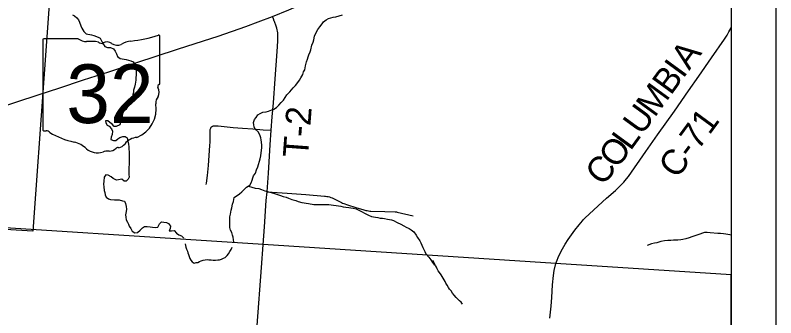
# Model space of a CAD drawing. Extents: x -8.2 to 34, y 0 to 22.
# Drawn here: x 7.291 to 9, y 15.27 to 15.949 of the extents above; entities that cross this region are included whole.
import ezdxf

# ---------------------------------------------------------------- set-up
doc = ezdxf.new("R2010")
doc.units = 0
for name, color, linetype in [('GM_X_Corporation', 7, 'Continuous'), ('GM_X_County_Road', 7, 'Continuous'), ('GM_X_County_Road_Text', 7, 'Continuous'), ('GM_X_Minor_River', 7, 'Continuous'), ('GM_X_State_Location', 7, 'Continuous'), ('GM_X_State_Route', 7, 'Continuous'), ('GM_X_State_Shield', 7, 'Continuous'), ('GM_X_Township_Road', 7, 'Continuous'), ('GM_X_Township_Road_Text', 7, 'Continuous'), ('GM_X_Township_Text', 7, 'Continuous'), ('SH_Data', 7, 'Continuous')]:
    doc.layers.add(name, color=color, linetype=linetype)

msp = doc.modelspace()

# ---------------------------------------------------------------- linework, layer by layer
at = {"layer": 'GM_X_Corporation'}
for points in [[(6.3752, 16.558), (7.4018, 16.494), (7.4044, 16.4939), (7.3299, 15.4643), (6.2993, 15.5265)], [(4.1481, 14.1), (8.9, 14.1), (8.9, 15.3663), (8.5054, 15.392), (7.8479, 15.4343), (7.082, 15.4841), (6.7558, 15.5053), (6.7389, 15.5064), (6.2987, 15.5287), (5.4088, 15.5882), (4.4836, 15.6492), (4.4152, 15.6505), (4.2922, 15.6569), (4.2674, 15.658), (4.2558, 15.6585), (4.2352, 15.4906), (4.2113, 15.0848), (4.1846, 14.6878), (4.1741, 14.5315), (4.1604, 14.3288)]]:
    msp.add_lwpolyline(points, close=True, dxfattribs=at)
at = {"layer": 'GM_X_County_Road'}
for points in [[(8.5057, 15.3914), (8.5086, 15.3992), (8.5112, 15.4049), (8.5165, 15.4161), (8.5207, 15.4244), (8.5269, 15.4351), (8.5334, 15.4456), (8.5408, 15.4564), (8.5482, 15.4663), (8.5579, 15.4784), (8.5655, 15.4874), (8.5681, 15.4903), (8.571, 15.4932), (8.5812, 15.5032), (8.6195, 15.5385), (8.6396, 15.556), (8.6487, 15.5645), (8.6531, 15.5689), (8.6582, 15.5744), (8.6642, 15.5815), (8.6687, 15.5874), (8.7079, 15.6433), (8.7339, 15.6804), (8.7721, 15.7341), (8.8039, 15.7793), (8.8268, 15.8125), (8.8553, 15.8539), (8.8847, 15.8956), (8.8904, 15.9044), (8.8948, 15.912), (8.8986, 15.9192), (8.9, 15.9225)], [(8.4924, 15.2686), (8.4953, 15.2956), (8.4969, 15.3155), (8.4978, 15.3438), (8.5001, 15.3647), (8.5018, 15.3762), (8.5057, 15.3914)]]:
    msp.add_lwpolyline(points, dxfattribs=at)
at = {"layer": 'GM_X_Minor_River'}
for points in [[(7.4191, 15.9504), (7.424, 15.9481), (7.4289, 15.9435), (7.4327, 15.9386), (7.4349, 15.9336), (7.4383, 15.9252), (7.4406, 15.9199), (7.4451, 15.913), (7.4504, 15.9077), (7.4618, 15.9053), (7.4671, 15.9041), (7.477, 15.9003), (7.4819, 15.8976), (7.4856, 15.8904), (7.4883, 15.8854), (7.4924, 15.8793), (7.4977, 15.8766), (7.505, 15.8766), (7.5118, 15.8735), (7.5152, 15.8689), (7.5186, 15.8624), (7.5208, 15.8563), (7.5265, 15.8521), (7.5402, 15.8497), (7.5504, 15.8466), (7.5554, 15.8447), (7.5595, 15.8394), (7.5606, 15.8337), (7.5617, 15.8283), (7.5625, 15.8219), (7.5624, 15.8146), (7.5616, 15.8093), (7.5616, 15.8036), (7.56, 15.7945), (7.5588, 15.788), (7.5565, 15.7808), (7.5561, 15.7758), (7.5553, 15.7713), (7.5542, 15.7667), (7.553, 15.7618), (7.5507, 15.7561), (7.548, 15.7496), (7.543, 15.7432), (7.5392, 15.7375), (7.5346, 15.7337), (7.5315, 15.7288), (7.5307, 15.7231), (7.5303, 15.7155), (7.5276, 15.7086), (7.5257, 15.7033), (7.5173, 15.6992), (7.5127, 15.6992), (7.5082, 15.7045), (7.5036, 15.708), (7.4987, 15.7118), (7.4934, 15.7119), (7.4941, 15.7073), (7.4971, 15.7027), (7.5021, 15.7), (7.5073, 15.6943), (7.5096, 15.6886), (7.5088, 15.6813), (7.5061, 15.6753), (7.5053, 15.6699), (7.5114, 15.6676), (7.5167, 15.668), (7.5213, 15.6714), (7.5259, 15.6748), (7.5323, 15.677), (7.5377, 15.6766), (7.5422, 15.6736), (7.5441, 15.6667), (7.5456, 15.6595), (7.5459, 15.6538), (7.5463, 15.6484), (7.547, 15.6427), (7.5469, 15.634), (7.5465, 15.6264)], [(7.7815, 15.4394), (7.7816, 15.4402), (7.7812, 15.4448), (7.7805, 15.4505), (7.779, 15.4555), (7.7772, 15.4612), (7.7745, 15.4665), (7.773, 15.4722), (7.7727, 15.4806), (7.7727, 15.4852), (7.7731, 15.4909), (7.7732, 15.4962), (7.7743, 15.5023), (7.7751, 15.5069), (7.7763, 15.5114), (7.7775, 15.5164), (7.779, 15.5247), (7.7814, 15.5308), (7.7829, 15.5403), (7.7944, 15.5478), (7.7997, 15.5528), (7.8051, 15.5581), (7.8108, 15.563), (7.8177, 15.5675), (7.8208, 15.5728), (7.8235, 15.5785), (7.8243, 15.5838), (7.8262, 15.5884), (7.8308, 15.5948), (7.8331, 15.6021), (7.8362, 15.6085), (7.8377, 15.6138), (7.8393, 15.6218), (7.8412, 15.6268), (7.8428, 15.6336), (7.8436, 15.6401), (7.8452, 15.6515), (7.8448, 15.6579), (7.8434, 15.6694), (7.8426, 15.6743), (7.8404, 15.6808), (7.8363, 15.6873), (7.8302, 15.6934), (7.828, 15.6987), (7.8268, 15.7033), (7.8261, 15.7086), (7.8284, 15.7151), (7.8323, 15.7196), (7.8361, 15.7257), (7.8411, 15.7287), (7.8475, 15.7314), (7.8544, 15.7325), (7.8597, 15.734), (7.8673, 15.737), (7.8719, 15.7381), (7.8776, 15.7419), (7.8834, 15.7475), (7.8883, 15.7532), (7.8933, 15.7589), (7.8972, 15.7642), (7.9014, 15.7703), (7.9079, 15.7771), (7.9117, 15.782), (7.9152, 15.7866), (7.9205, 15.7915), (7.9255, 15.7983), (7.9293, 15.8036), (7.9328, 15.8085), (7.937, 15.8165), (7.9389, 15.8218), (7.9412, 15.8268), (7.942, 15.8313), (7.9428, 15.8359), (7.9451, 15.8446), (7.9475, 15.8503), (7.949, 15.8557), (7.9506, 15.8606), (7.9533, 15.867), (7.9548, 15.8716), (7.9575, 15.8819), (7.9599, 15.8891), (7.9618, 15.8944), (7.9634, 15.902), (7.9672, 15.9107), (7.9707, 15.9176), (7.9749, 15.9229), (7.9802, 15.9297), (7.9833, 15.9346), (7.9894, 15.9392), (7.9951, 15.9422), (8.0001, 15.9437), (8.0054, 15.9448), (8.0111, 15.9459), (8.0188, 15.9481), (8.026, 15.95)], [(7.5465, 15.6264), (7.5464, 15.6134), (7.546, 15.6089), (7.546, 15.602), (7.5463, 15.5917), (7.5467, 15.5856), (7.5447, 15.5811), (7.5398, 15.5765), (7.5352, 15.5769), (7.5299, 15.5808), (7.5227, 15.5797), (7.5181, 15.5789), (7.5109, 15.5828), (7.506, 15.5866), (7.4999, 15.5901), (7.4942, 15.5905), (7.4908, 15.5855), (7.4896, 15.5764), (7.4891, 15.5699), (7.4895, 15.5639), (7.4906, 15.5559), (7.4917, 15.5513), (7.4928, 15.546), (7.4947, 15.5406), (7.5004, 15.5372), (7.5049, 15.5352), (7.5137, 15.5348), (7.5239, 15.5348), (7.5315, 15.5328), (7.5365, 15.5317), (7.5383, 15.5263), (7.5402, 15.5195), (7.5405, 15.5141), (7.5397, 15.5084), (7.5386, 15.5008), (7.5393, 15.4955), (7.54, 15.4898), (7.543, 15.4848), (7.5449, 15.4799), (7.5468, 15.4753), (7.5502, 15.4703), (7.5536, 15.4642), (7.5592, 15.4604), (7.5657, 15.4611), (7.5715, 15.4664), (7.5764, 15.4717), (7.5814, 15.4751), (7.5871, 15.4747), (7.5939, 15.4743), (7.5993, 15.4735), (7.6065, 15.4723), (7.611, 15.4731), (7.6149, 15.4807), (7.6191, 15.4852), (7.6248, 15.4848), (7.6305, 15.4836), (7.6354, 15.4817), (7.64, 15.4756), (7.6388, 15.4706), (7.6369, 15.4653), (7.6418, 15.4653), (7.6475, 15.466), (7.6528, 15.4599), (7.6585, 15.4561), (7.6642, 15.4541), (7.6691, 15.4492), (7.6692, 15.4489)], [(7.8148, 15.5656), (7.8302, 15.5606), (7.8382, 15.5598), (7.8443, 15.5579), (7.8518, 15.5552), (7.8579, 15.5536), (7.8629, 15.5521), (7.8682, 15.5501), (7.8731, 15.549), (7.8822, 15.5459), (7.8872, 15.5443), (7.8925, 15.5424), (7.8993, 15.5405), (7.9046, 15.5385), (7.9126, 15.5358), (7.9213, 15.5331), (7.9266, 15.5312), (7.935, 15.5289), (7.9399, 15.5281), (7.9445, 15.5269), (7.9498, 15.5261), (7.962, 15.5245), (7.9673, 15.5241), (7.9768, 15.5241), (7.9829, 15.5244), (7.9909, 15.5244), (7.9954, 15.524), (8.0004, 15.5236), (8.0061, 15.5228), (8.0121, 15.522), (8.0171, 15.5212), (8.0224, 15.5204), (8.0277, 15.5193), (8.0338, 15.5185), (8.0403, 15.5177), (8.0452, 15.5169), (8.0498, 15.5161), (8.057, 15.5142), (8.0646, 15.5107), (8.0691, 15.5088), (8.0774, 15.5042), (8.0846, 15.5003), (8.0911, 15.4976), (8.1002, 15.4957), (8.1055, 15.4949), (8.1112, 15.4937), (8.1162, 15.4933), (8.1207, 15.4925), (8.1272, 15.4914), (8.1363, 15.4894), (8.1409, 15.4879), (8.1492, 15.484), (8.1572, 15.4802), (8.1644, 15.4763), (8.1693, 15.4733), (8.1757, 15.4702), (8.1807, 15.4671), (8.1867, 15.4625), (8.192, 15.4557), (8.1946, 15.4503), (8.2003, 15.4427), (8.2026, 15.4381), (8.2044, 15.4331), (8.2071, 15.4278), (8.2093, 15.4228), (8.2112, 15.4183), (8.2138, 15.4137), (8.2199, 15.4057), (8.2244, 15.3996), (8.2282, 15.3942), (8.2331, 15.3877)], [(8.9, 15.4556), (8.8967, 15.4559), (8.8879, 15.4575), (8.8822, 15.4582), (8.8754, 15.459), (8.8697, 15.4594), (8.8522, 15.4603), (8.8461, 15.4611), (8.84, 15.4611), (8.8351, 15.46), (8.8294, 15.4577), (8.8202, 15.4547), (8.8111, 15.4514), (8.8054, 15.4495), (8.7981, 15.4473), (8.7913, 15.4454), (8.7867, 15.4446), (8.7799, 15.4443), (8.7753, 15.4443), (8.77, 15.444), (8.7639, 15.4436), (8.757, 15.4437), (8.7498, 15.4429), (8.7418, 15.4411), (8.733, 15.4384), (8.7273, 15.4373), (8.7209, 15.4358), (8.7106, 15.4325)], [(7.6725, 15.4359), (7.674, 15.4284), (7.6756, 15.4239), (7.6775, 15.4197), (7.6783, 15.4155), (7.6798, 15.4117), (7.6813, 15.4072), (7.6832, 15.403), (7.6855, 15.3992), (7.6882, 15.3954), (7.6928, 15.3928), (7.6973, 15.3936), (7.7011, 15.3943), (7.7049, 15.3962), (7.7087, 15.3974), (7.7129, 15.3993), (7.7174, 15.3997), (7.7224, 15.4008), (7.7261, 15.4001), (7.7311, 15.4001), (7.7356, 15.399), (7.741, 15.399), (7.7463, 15.3998), (7.7501, 15.3998), (7.7539, 15.4013), (7.7588, 15.4036), (7.7626, 15.4051), (7.7671, 15.4093), (7.7702, 15.4135), (7.7732, 15.4184), (7.7762, 15.423), (7.778, 15.4287)], [(8.296, 15.3002), (8.2926, 15.3048), (8.2888, 15.3082), (8.285, 15.312), (8.2815, 15.3157), (8.277, 15.3203), (8.2732, 15.3252), (8.2701, 15.3301), (8.2667, 15.3343), (8.2644, 15.3381), (8.2617, 15.343), (8.2583, 15.3472), (8.2568, 15.351), (8.2549, 15.3548), (8.2522, 15.3589), (8.2503, 15.3627), (8.248, 15.3665), (8.2442, 15.3714), (8.2411, 15.3752), (8.2392, 15.3794), (8.2373, 15.3832), (8.235, 15.3873), (8.2292, 15.3983)]]:
    msp.add_lwpolyline(points, dxfattribs=at)
at = {"layer": 'GM_X_State_Route'}
msp.add_lwpolyline([(7.2201, 15.7306), (7.2917, 15.7539), (7.3441, 15.7709), (7.3883, 15.7856), (7.4441, 15.8039), (7.5008, 15.8224), (7.5616, 15.8421), (7.6557, 15.8731), (7.714, 15.8919), (7.7468, 15.9025), (7.8086, 15.9239), (7.8367, 15.9344), (7.8688, 15.9467), (7.9053, 15.9614), (7.935, 15.9739), (7.9627, 15.9861), (7.9967, 16.0017), (8.0093, 16.0077)], dxfattribs=at)
at = {"layer": 'GM_X_State_Shield'}
for p, q in [((7.616, 15.7968), (7.616, 15.9015)), ((7.3524, 15.8931), (7.3524, 15.693)), ((7.4322, 15.8966), (7.355, 15.8966)), ((7.616, 15.7969), (7.616, 15.7968))]:
    msp.add_line(p, q, dxfattribs=at)
for centre, radius, start, end in [((7.5221, 16.1694), 0.2796, 275.8445, 288.9065), ((7.6131, 15.902), 0.00294, 351.8621, 97.738), ((7.3554, 15.8935), 0.00305, 98.1301, 188.1301), ((7.4506, 15.9198), 0.0296, 231.6195, 271.1119), ((7.4604, 15.7842), 0.1064, 80.4867, 94.9883), ((7.4846, 15.8946), 0.00855, 219.7921, 297.1024), ((7.4971, 15.8715), 0.0178, 54.4667, 119.1411), ((7.52, 15.9032), 0.0214, 233.8562, 294.8282), ((7.5578, 15.8354), 0.0563, 97.3462, 120.7689), ((7.6129, 15.7964), 0.00314, 289.6038, 7.7341), ((7.6154, 15.7892), 0.00454, 107.944, 210.337), ((7.5865, 15.7759), 0.0273, 340.033, 23.6496), ((7.6266, 15.753), 0.0198, 136.8065, 186.9296), ((7.5378, 15.7397), 0.0699, 292.3089, 8.9858), ((7.3554, 15.6926), 0.00308, 171.9584, 258.3066), ((7.3559, 15.713), 0.0235, 267.339, 280.6039), ((7.3607, 15.6815), 0.00848, 29.7484, 93.2717), ((7.4678, 15.8613), 0.2019, 240.4129, 257.1985), ((7.5673, 15.6368), 0.0383, 94.4031, 142.5768), ((7.4076, 15.6031), 0.0632, 47.1842, 75.836), ((7.5187, 15.6736), 0.0226, 282.8732, 323.2771), ((7.4759, 15.6805), 0.0401, 230.7004, 286.2918), ((7.4991, 15.6113), 0.0329, 85.6951, 111.2099), ((7.502, 15.6655), 0.0214, 268.777, 315.5493), ((7.5213, 15.6461), 0.00601, 65.7517, 132.6484)]:
    msp.add_arc(centre, radius, start, end, dxfattribs=at)
at = {"layer": 'GM_X_Township_Road'}
for points in [[(7.8727, 15.9363), (7.8709, 15.9409), (7.8688, 15.9467)], [(7.879, 15.8677), (7.8806, 15.8908), (7.8809, 15.8951), (7.8812, 15.8997), (7.8812, 15.9028), (7.8811, 15.9058), (7.8808, 15.91), (7.8803, 15.9135), (7.8797, 15.9166), (7.8786, 15.9205), (7.877, 15.9251), (7.8731, 15.9353), (7.8727, 15.9363)], [(7.8481, 15.4338), (7.8507, 15.4741), (7.855, 15.5332), (7.8567, 15.5527), (7.8597, 15.5944), (7.864, 15.6584), (7.866, 15.6908), (7.8684, 15.721), (7.8709, 15.7523), (7.8748, 15.8065), (7.879, 15.8677)], [(7.72, 15.5688), (7.7204, 15.5724), (7.7228, 15.5893), (7.7248, 15.6116), (7.7281, 15.6564), (7.7281, 15.6578), (7.7286, 15.6638), (7.7287, 15.6656), (7.7287, 15.6893), (7.7288, 15.6912), (7.7291, 15.693), (7.7294, 15.6944), (7.73, 15.6958), (7.7305, 15.6968), (7.731, 15.6974), (7.7318, 15.6983), (7.7329, 15.6992), (7.7338, 15.6998), (7.735, 15.7004), (7.7366, 15.7008), (7.7382, 15.701), (7.7404, 15.7011), (7.7428, 15.7009), (7.7471, 15.7006), (7.7802, 15.6973), (7.8014, 15.6955), (7.8243, 15.6939), (7.848, 15.6918), (7.866, 15.6908)], [(7.8567, 15.5527), (7.9015, 15.5498), (7.944, 15.5464), (7.9857, 15.5431), (7.9883, 15.5429), (7.9912, 15.5425), (7.9939, 15.5419), (7.9967, 15.5411), (7.9996, 15.5402), (8.0027, 15.5389), (8.0076, 15.5367), (8.0207, 15.53), (8.024, 15.5284), (8.0265, 15.5274), (8.0292, 15.5263), (8.0373, 15.5234), (8.0565, 15.5172), (8.0742, 15.5121), (8.079, 15.511), (8.0817, 15.5105), (8.0845, 15.51), (8.0874, 15.5096), (8.0902, 15.5093), (8.1213, 15.5086), (8.1443, 15.508), (8.1458, 15.5078), (8.1472, 15.5075), (8.1488, 15.5072), (8.1847, 15.4985)], [(7.8346, 15.2527), (7.8439, 15.3826), (7.8481, 15.4338)]]:
    msp.add_lwpolyline(points, dxfattribs=at)
at = {"layer": 'GM_X_Township_Text'}
msp.add_lwpolyline([(8.9, 15.3663), (8.5054, 15.392), (7.8479, 15.4343), (7.082, 15.4841), (6.7558, 15.5053), (6.7389, 15.5064), (6.2987, 15.5287), (5.4088, 15.5882), (4.4836, 15.6492), (4.4152, 15.6505), (4.2922, 15.6569), (4.2674, 15.658), (4.2558, 15.6585), (4.2352, 15.4906), (4.2113, 15.0848), (4.1846, 14.6878), (4.1741, 14.5315), (4.1604, 14.3288), (4.1481, 14.1)], dxfattribs=at)
at = {"layer": 'SH_Data'}
for p, q in [((9, 21), (9, 14)), ((8.9, 20.9), (8.9, 14.1))]:
    msp.add_line(p, q, dxfattribs=at)

# ---------------------------------------------------------------- texts
at = {"layer": 'GM_X_County_Road_Text'}
for s, height, rotation, p in [('A', 0.0568, 53.2168, (8.8053, 15.8241)), ('I', 0.0568, 53.929, (8.7916, 15.8054)), ('B', 0.0568, 53.9267, (8.7641, 15.7677)), ('M', 0.0568, 53.9311, (8.7278, 15.7179)), ('U', 0.0568, 53.9306, (8.6984, 15.6775)), ('C-71', 0.05682, 53.7484, (8.7782, 15.5798)), ('L', 0.0568, 53.9293, (8.6734, 15.6431)), ('O', 0.0568, 53.2941, (8.6431, 15.6025)), ('C', 0.0568, 49.2526, (8.6099, 15.5637))]:
    msp.add_text(s, height=height, rotation=rotation, dxfattribs=at).set_placement(p)
at = {"layer": 'GM_X_State_Location'}
for s in ['s', 'r']:
    msp.add_text(s, height=0.000189, dxfattribs=at).set_placement((7.4812, 15.7798))
msp.add_text('32', height=0.000189, rotation=0, dxfattribs=at).set_placement((7.4336, 15.766))
at = {"layer": 'GM_X_State_Shield'}
msp.add_text('32', height=0.13184, dxfattribs=at).set_placement((7.4055, 15.7071))
at = {"layer": 'GM_X_Township_Road_Text'}
msp.add_text('T-2', height=0.05682, rotation=85.7113, dxfattribs=at).set_placement((7.9486, 15.6283))

doc.saveas('drawing.dxf')
